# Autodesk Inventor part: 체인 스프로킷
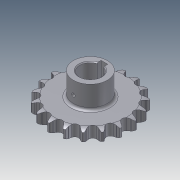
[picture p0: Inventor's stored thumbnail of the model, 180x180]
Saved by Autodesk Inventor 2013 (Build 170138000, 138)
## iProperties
Created: 2014-07
Part Number: 체인 스프로킷
Material: 스테인리스강
Document SubType Name: Modeling
Designer: KYOUNG IL JANG
Density: 8.08 g/cm^3
Mass: 760.268 g
Surface Area: 236.854 cm^2
Volume: 94.0925 cm^3
CustomPartVersion: 1
Company: 한국ATC센터
Author: KYOUNG IL JANG
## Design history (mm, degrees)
sketch "이론적 톱니 프로파일"
  geometry: L1 (0, 0)-(0, 45.567); L2 (0, 0)-(14.795, 43.098); L3 (0, 45.567)-(14.795, 43.098); L4 (0, 45.567)-(5.661, 50.015); L5 (5.661, 50.015)-(-5.141, 45.406); L6 (-12.428, 43.493)-(-5.573, 46.417); L7 (-5.141, 45.406)-(-5.573, 46.417); L8 (5.573, 46.417)-(5.141, 45.406); L9 (0, 0)-(8.138, 48.771); A1 r 45.567 centre (0, 0) between (0, 45.567) and (14.795, 43.098); A2 r 49.445 centre (0, 0) between (7.302, 48.903) and (-7.302, 48.903); A3 r 4.545 centre (0, 45.567) between (-3.574, 42.758) and (3.574, 42.758); A4 r 7.453 centre (12.428, 43.493) between (7.302, 48.903) and (5.573, 46.417); A5 r 7.453 centre (-12.428, 43.493) between (-5.573, 46.417) and (-7.302, 48.903); A6 r 11.745 centre (5.661, 50.015) between (-5.141, 45.406) and (-3.574, 42.758); A7 r 11.745 centre (-5.661, 50.015) between (3.574, 42.758) and (5.141, 45.406); 2 further points
  constraints: 18 end point, 15 point on circle, 7 centre point, 3 coincident, 3 point on line, 3 symmetric about line, 3 tangent, 1 equal radius, 1 midpoint, 1 parallel, 1 vertical, 1 other
  dimensions: "d0" = 91.13301 diameter of A1 (computed from da_p, da_z); "d2" = 18.9474 deg angle of L2 L1 (computed from da_z); "d3" = 4.545 radius of A3 (= 0.5 x da_Dr + da_SC); "d10" = 128.158 deg angle of L4 L1 (computed from da_z); "d11" = 15.0526 deg angle of L5 L4 (computed from da_z); "d12" = 7.2 distance of L3.start L4.end (= 0.8 x da_Dr); "d13" = 11.745 distance of L4.end L5.end (= 1.3 x da_Dr + da_SC); "d14" = 12.6 distance of A4.centre L1.end (= 1.4 x da_Dr); "d23" = 4.5 distance from line of L9.end L3 (= da_Ha)
sketch "톱니 프로파일"
  geometry: L1 (0, 0)-(0, 45.567); L2 (0, 45.567)-(4.203, 43.837); L3 (0, 45.567)-(-4.203, 43.837); A1 r 4.545 centre (0, 45.567) between (-4.203, 43.837) and (4.203, 43.837); A2 r 22.68 centre (25.176, 35.206) between (7.12, 48.93) and (4.203, 43.837); A3 r 22.68 centre (-25.176, 35.206) between (-4.203, 43.837) and (-7.12, 48.93); A4 r 49.445 centre (0, 0) between (-7.12, 48.93) and (7.12, 48.93) reference; 1 further point
  constraints: 9 point on circle, 6 end point, 3 centre point, 2 tangent, 1 coincident, 1 equal radius, 1 vertical, 1 other
  dimensions: "d44" = 135.263 deg angle of L3 L2 (= da_Alfa); "d45" = 22.68 radius of A2 (= da_Re); "d46" = 4.545 radius of A1 (= da_Ri)
sketch "단면 프로파일"
  geometry: L1 (49.445, 0)-(-49.445, 0) reference; L2 (33.265, 6.65)-(-33.265, 6.65); L3 (-33.265, 6.65)-(-33.265, -6.65); L4 (-33.265, -6.65)-(33.265, -6.65); L5 (33.265, -6.65)-(33.265, 6.65); L6 (33.265, 6.65)-(49.445, 6.65); L7 (49.445, 6.65)-(49.445, -6.65); L8 (49.445, -6.65)-(33.265, -6.65); L9 (33.265, -6.65)-(33.265, 6.65); L10 (42.183, 6.65)-(0, 6.65); L11 (0, 6.65)-(0, -6.65); L12 (0, -6.65)-(42.183, -6.65); L13 (0, 6.65)-(0, -6.65); L14 (49.445, 4.775)-(49.445, -4.775); A1 r 15 centre (42.183, -8.35) between (49.445, 4.775) and (42.183, 6.65); A2 r 15 centre (42.183, 8.35) between (42.183, -6.65) and (49.445, -4.775); 2 further points
  constraints: 26 end point, 7 midpoint, 5 perpendicular, 4 parallel, 4 point on circle, 3 point on line, 3 symmetric about line, 2 centre point, 2 horizontal, 2 tangent, 1 collinear, 1 other
  dimensions: "d30" = 13.3 distance between parallel lines of L8 L6 (= da_Bf); "d31" = 66.53007 distance between parallel lines of L3 L5 (= da_Ds); "d32" = 13.3 distance between parallel lines of L4 L2 (= da_Bs); "d33" = 1.875 distance from line of L14.start L6 (= da_Ba); "d34" = 15 radius of A1 (= da_Rx); "d43" = 6.65 distance between parallel lines of L4 L1 (computed from da_k, da_pt, da_Bs)
revolve "슈라우드" stored, may be unused: angle "d36" = 90 deg
revolve "스트랜드" stored, may be unused: angle "d37" = 90 deg
extrude "이론적 톱니" cut sketch "이론적 톱니 프로파일" stored distance "d18" = 10; taper "d19" = 0 deg; dims "d49" = 0, "form_type" = 0 [user parameter]
extrude "톱니" cut sketch "톱니 프로파일" stored distance "d47" = 10; taper "d48" = 0 deg; dims "d50" = 10, "form_type" = 0 [user parameter]
node "타이밍 평면"
node "작업 평면3"
sketch "스케치5"
  geometry: C1 r 20 at (0, -45.567); 1 further point
  constraints: 1 centre point, 1 coincident
  dimensions: "d52" = 40 diameter of C1
extrude "돌출4" join sketch "스케치5" stored distance "d53" = 10; taper "d54" = 0 deg
sketch "스케치6"
  geometry: L1 (4, 11.843)-(4, 16.5); L2 (4, 16.5)-(-4, 16.5); L3 (-4, 16.5)-(-4, 11.843); A1 r 12.5 centre (0, 0) between (4, 11.843) and (-4, 11.843); 1 further point
  constraints: 6 end point, 2 parallel, 2 point on circle, 1 centre point, 1 coincident, 1 perpendicular, 1 vertical
  dimensions: "d55" = 25 diameter of A1; "d56" = 29 dimension on A1 L2 (computed from d55); "d57" = 8 distance of L1.end L2.end
extrude "돌출5" cut sketch "스케치6" stored distance "d58" = 10; taper "d59" = 0 deg
fillet "모깎기2" dims "d60" = 3
chamfer "모따기1" distance "d61" = 1; stored, may be unused: second distance "d62" = 2, angle "d63" = 45 deg
node "작업 평면4"
sketch "스케치7"
  geometry: L1 (-13.5, -13.3)-(13.5, -13.3) reference; 4 further points
  constraints: 1 vertical alignment
  dimensions: "d65" = 25 distance from line of point (0, 11.7) L1
hole "구멍1" sketch "스케치7" at (0, 11.7) diameter "d66" = 4.134; stored, may be unused: countersink angle "d70" = 90 deg, drill point angle "d72" = 118 deg; dims "d67" = 6, "d68" = 4, "d69" = 2, "d71" = 8
body "Solid1"
pattern_linear "스트랜드 패턴" dims "d40" = 24 (= da_pt)
pattern_circular "톱니 패턴" dims angle "d21" = 360 deg
other parameters: "da_p" = 15 [user parameter; used in 1 equation term], "da_Dr" = 9 [user parameter; used in 4 equation terms], "da_SC" = 0.045 [user parameter; used in 2 equation terms], "da_Ha" = 4.5 [user parameter; used in 1 equation term], "da_pt" = 24 [user parameter; used in 2 equation terms], "da_Bf" = 13.3 [user parameter; used in 1 equation term], "d28" = 0, "d29" = 0, "da_Ba" = 1.875 [user parameter; used in 1 equation term], "da_Rx" = 15 [user parameter; used in 1 equation term], "da_Ra" = 0.6 [user parameter], "da_Bs" = 13.3 [user parameter; used in 2 equation terms], "da_Ds" = 66.53007 [user parameter; used in 1 equation term], "d42" = 0, "da_Re" = 22.68 [user parameter; used in 1 equation term], "da_Ri" = 4.545 [user parameter; used in 1 equation term], "da_Alfa" = 135.263 deg [user parameter; used in 1 equation term]
